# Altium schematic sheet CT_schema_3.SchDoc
size 283 x 135 mm
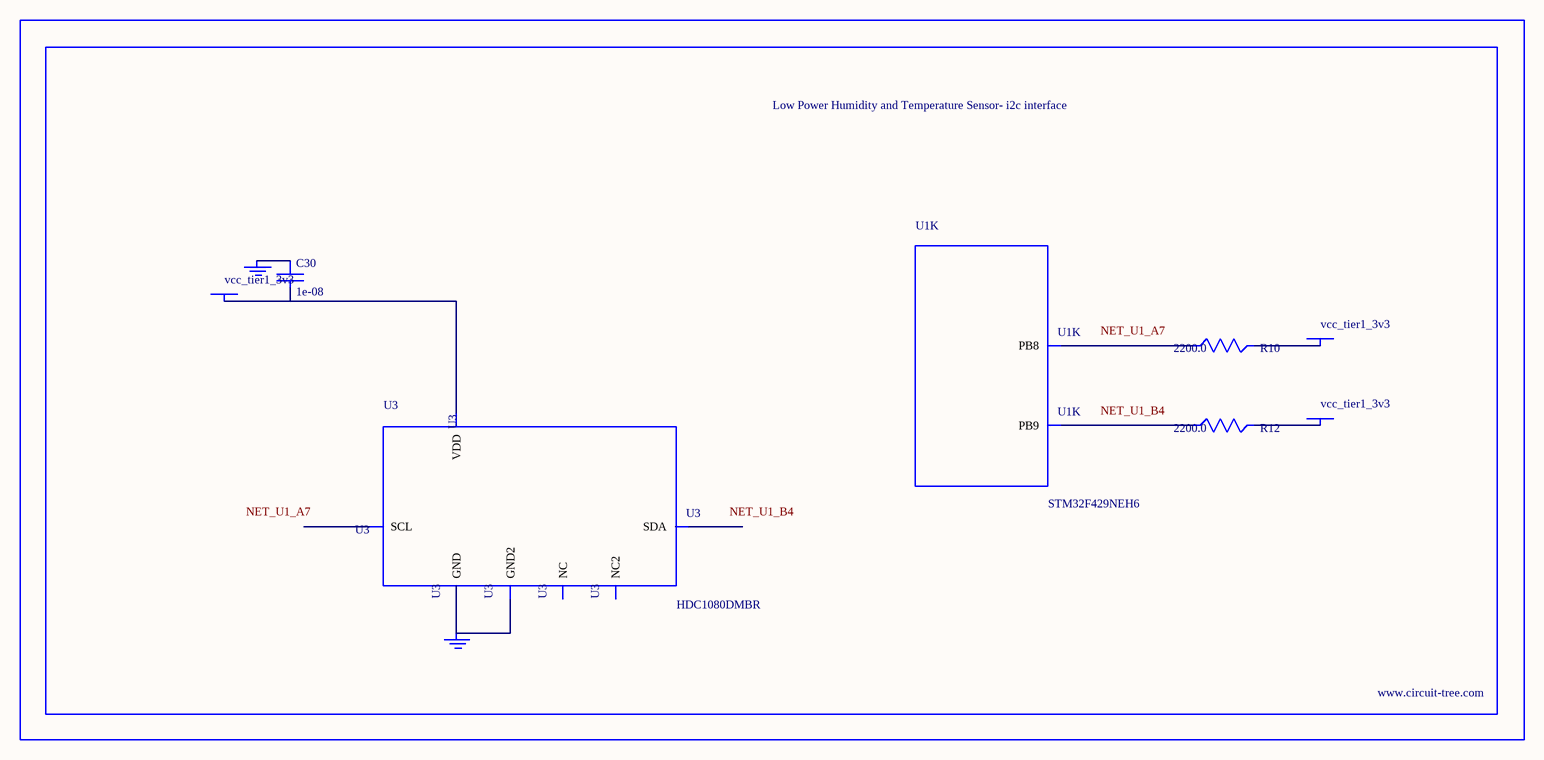
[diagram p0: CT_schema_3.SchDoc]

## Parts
BORDER2  (no value)
C30  1e-08  [C0402]
GND_INSTANCE_2_0  (no value)
GND_INSTANCE_2_1  (no value)
POWER_INSTANCE_2_0  vcc_tier1_3v3
POWER_INSTANCE_2_1  vcc_tier1_3v3
POWER_INSTANCE_2_2  vcc_tier1_3v3
R10  2200.0  [R0603]
R12  2200.0  [R0603]
U1  STM32F429NEH6  [TFBGA216]  (part K of 17)
U3  HDC1080DMBR  [WSON-6]

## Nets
NetC30_1: C30.1 GND_INSTANCE_2_0.0(GND)
NetC30_2: C30.2 POWER_INSTANCE_2_0.0(PWR) U3.5(VDD)
NetGND_INSTANCE_2_1_0: GND_INSTANCE_2_1.0(GND) U3.2(GND) U3.PAD(GND2)
NetPOWER_INSTANCE_2_1_0: POWER_INSTANCE_2_1.0(PWR) R10.2
NetPOWER_INSTANCE_2_2_0: POWER_INSTANCE_2_2.0(PWR) R12.2
NetR10_1: R10.1 U1.A7(PB8)
NetR12_1: R12.1 U1.B4(PB9)

Not connected (* = marked no-connect by the designer): U3 1(SDA) 3(NC) 4(NC2) 6(SCL)

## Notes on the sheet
- Labels drawn without touching a wire or pin: NET_U1_A7, NET_U1_B4

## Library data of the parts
BORDER2 = BORDER_PAGE2
C30 = C0402C103K3RAC
GND_INSTANCE_2_0 GND_INSTANCE_2_1 = GND
POWER_INSTANCE_2_0-POWER_INSTANCE_2_2 = PWR
R10 R12 = RC0603JR-072K2L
